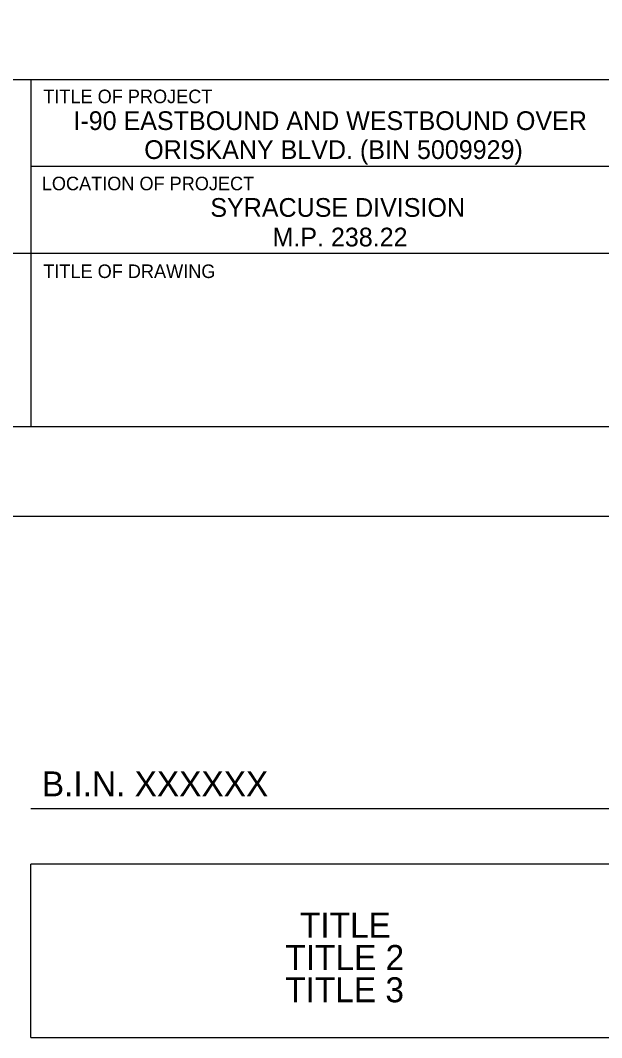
# Model space of a CAD drawing. Extents: x -0.04 to 1.42, y -0.15 to 0.92.
# Drawn here: x 1.1453 to 1.285, y -0.1253 to 0.1191 of the extents above; entities that cross this region are included whole.
import ezdxf

# ---------------------------------------------------------------- set-up
doc = ezdxf.new("R2010")
doc.units = 0
for name, color, linetype in [('SHEET_BORDER', 7, 'Continuous'), ('SHEET_BORDER_EDGE', 7, 'Continuous'), ('SHEET_BORDER_TEXT', 7, 'Continuous'), ('SHEET_BORDER_TEXT_SHEETINFO', 7, 'Continuous')]:
    doc.layers.add(name, color=color, linetype=linetype)

# ---------------------------------------------------------------- blocks, each defined once
blk = doc.blocks.new('twy_border_sheet')
at = {"layer": 'SHEET_BORDER_EDGE'}
blk.add_lwpolyline([(0, -0.300743), (0.464785, -0.300743), (0.464785, 0), (0, 0)], close=True, dxfattribs=at)
blk = doc.blocks.new('NSB_SI')
at = {"layer": 'SHEET_BORDER_EDGE'}
blk.add_blockref('twy_border_sheet', (0, 0), dxfattribs=at)

msp = doc.modelspace()

# ---------------------------------------------------------------- linework, layer by layer
at = {"layer": 'SHEET_BORDER'}
for p, q in [((1.36458, 0.10482), (0.66497, 0.10482)), ((1.14779, 0.10482), (1.14779, 0.02148)), ((1.29753, 0.08398), (1.14779, 0.08398)), ((0.91471, 0.06315), (1.29753, 0.06315))]:
    msp.add_line(p, q, dxfattribs=at)
msp.add_lwpolyline([(1.36458, 0.02669), (1.35937, 0.02148), (0.05729, 0.02148), (0.05208, 0.02669), (0.05208, 0.88997), (0.05729, 0.89518), (1.35937, 0.89518), (1.36458, 0.88997)], close=True, dxfattribs=at)
at = {"layer": 'SHEET_BORDER_TEXT_SHEETINFO'}
for p, q in [((1.14779, -0.07024), (1.36458, -0.07024)), ((1.14779, -0.12526), (1.14779, -0.0836)), ((1.29753, -0.0836), (1.14779, -0.0836)), ((1.14779, -0.12526), (1.35937, -0.12526))]:
    msp.add_line(p, q, dxfattribs=at)

# ---------------------------------------------------------------- block references
at = {"layer": 'SHEET_BORDER', "xscale": 3.0480060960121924, "yscale": 3.0480060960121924}
msp.add_blockref('NSB_SI', (0, 0.91667), dxfattribs=at)

# ---------------------------------------------------------------- texts
at = {"layer": 'SHEET_BORDER'}
for s, p in [('TITLE OF PROJECT', (1.15079, 0.09921)), ('LOCATION OF PROJECT', (1.15043, 0.07829)), ('TITLE OF DRAWING', (1.15079, 0.05721))]:
    msp.add_text(s, height=0.0032552, dxfattribs=at).set_placement(p)
at = {"layer": 'SHEET_BORDER_TEXT'}
for s, height, p in [('SYRACUSE DIVISION', 0.0045, (1.19093, 0.07191)), ('B.I.N. XXXXXX', 0.006, (1.15044, -0.0673)), ('TITLE', 0.006, (1.21247, -0.10124)), ('TITLE 2', 0.006, (1.20896, -0.109)), ('TITLE 3', 0.006, (1.20892, -0.11676))]:
    msp.add_text(s, height=height, dxfattribs=at).set_placement(p)
at = {"layer": 'SHEET_BORDER_TEXT_SHEETINFO'}
for s, p in [('I-90 EASTBOUND AND WESTBOUND OVER', (1.15803, 0.09276)), ('ORISKANY BLVD. (BIN 5009929)', (1.17504, 0.0858)), ('M.P. 238.22', (1.20586, 0.0648))]:
    msp.add_text(s, height=0.0045, dxfattribs=at).set_placement(p)

doc.saveas('drawing.dxf')
